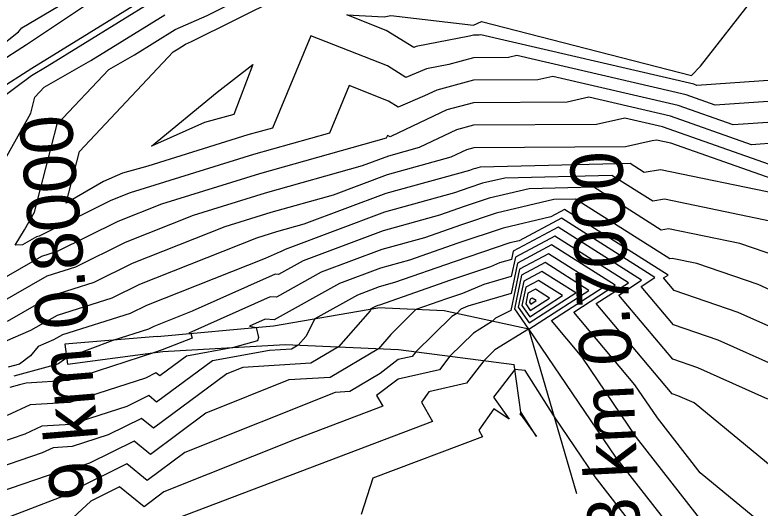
# Model space of a CAD drawing. Extents: x -549394 to -546608, y -1037055 to -1033629.
# Drawn here: x -548073.8 to -547944.9, y -1035661.2 to -1035575.9 of the extents above; entities that cross this region are included whole.
import ezdxf

# ---------------------------------------------------------------- set-up
doc = ezdxf.new("R2010")
doc.units = 0
for name, color, linetype in [('hlavni_vrst', 7, 'Continuous'), ('hrana_L', 7, 'Continuous'), ('norm_vrst', 7, 'Continuous'), ('x_popis_pricne_rezy_C1', 7, 'Continuous')]:
    doc.layers.add(name, color=color, linetype=linetype)

msp = doc.modelspace()

# ---------------------------------------------------------------- linework, layer by layer
at = {"layer": 'hlavni_vrst'}
for p, q in [((-548068.19, -1035584.8), (-548049.67, -1035573.38)), ((-548070.93, -1035586.38), (-548068.19, -1035584.8)), ((-548082.34, -1035594.86), (-548070.93, -1035586.38)), ((-547968.29, -1035593.77), (-547973.23, -1035594.84)), ((-547961.77, -1035595.29), (-547968.29, -1035593.77)), ((-547994.45, -1035595.01), (-547997.39, -1035595.8)), ((-547973.23, -1035594.84), (-547994.45, -1035595.01)), ((-547943.29, -1035601.77), (-547961.77, -1035595.29)), ((-547997.39, -1035595.8), (-548003.85, -1035598.87)), ((-548003.85, -1035598.87), (-548009.18, -1035600.33)), ((-548009.18, -1035600.33), (-548013.71, -1035602.03)), ((-548013.71, -1035602.03), (-548030.5, -1035606.72)), ((-548030.5, -1035606.72), (-548042.93, -1035610.58)), ((-547980.61, -1035607.84), (-547990.55, -1035610.18)), ((-547976.84, -1035607.75), (-547980.61, -1035607.84)), ((-547960.51, -1035618.09), (-547976.84, -1035607.75)), ((-548042.93, -1035610.58), (-548054.73, -1035615.26)), ((-547990.55, -1035610.18), (-547996.55, -1035612.2)), ((-547996.55, -1035612.2), (-548002.93, -1035614.44)), ((-548002.93, -1035614.44), (-548010.33, -1035616.48)), ((-548054.73, -1035615.26), (-548063.29, -1035619.52)), ((-547980.97, -1035615.67), (-547986.88, -1035618.83)), ((-547969.96, -1035622.66), (-547980.97, -1035615.67)), ((-548010.33, -1035616.48), (-548020.8, -1035620.4)), ((-547986.88, -1035618.83), (-547987.98, -1035624.07)), ((-547960.1, -1035618.02), (-547960.51, -1035618.09)), ((-547955.87, -1035618.9), (-547960.1, -1035618.02)), ((-547945.25, -1035622.54), (-547955.87, -1035618.9)), ((-548063.29, -1035619.52), (-548068.27, -1035621.07)), ((-548068.27, -1035621.07), (-548079.1, -1035627.29)), ((-548020.8, -1035620.4), (-548028.56, -1035624.69)), ((-547977.12, -1035627.29), (-547969.96, -1035622.66)), ((-547922.03, -1035632.93), (-547945.25, -1035622.54)), ((-547987.98, -1035624.07), (-547995.45, -1035626.25)), ((-547985.06, -1035624.02), (-547985.45, -1035625.88)), ((-547983.77, -1035623.33), (-547985.06, -1035624.02)), ((-547981.36, -1035624.86), (-547983.77, -1035623.33)), ((-548029.63, -1035624.63), (-548043.71, -1035630.91)), ((-548028.56, -1035624.69), (-548029.63, -1035624.63)), ((-547984.67, -1035627), (-547981.36, -1035624.86)), ((-547995.45, -1035626.25), (-547996.66, -1035626.76)), ((-547985.45, -1035625.88), (-547984.67, -1035627)), ((-547997.37, -1035627.53), (-547998.23, -1035628.07)), ((-547996.66, -1035626.76), (-547997.37, -1035627.53)), ((-547966.56, -1035639.84), (-547977.12, -1035627.29)), ((-547998.23, -1035628.07), (-548004.47, -1035634.15)), ((-548043.13, -1035631.77), (-548048.33, -1035633.81)), ((-548043.71, -1035630.91), (-548043.33, -1035630.98)), ((-548043.33, -1035630.98), (-548043.13, -1035631.77)), ((-548049.61, -1035634.3), (-548064.51, -1035639.13)), ((-548048.33, -1035633.81), (-548049.61, -1035634.3)), ((-548004.47, -1035634.15), (-548005.08, -1035634.94)), ((-548007.48, -1035635.49), (-548010.63, -1035637.9)), ((-548005.08, -1035634.94), (-548007.48, -1035635.49)), ((-548010.63, -1035637.9), (-548015.88, -1035641.02)), ((-548071.82, -1035639.55), (-548072.98, -1035639.86)), ((-548064.51, -1035639.13), (-548071.82, -1035639.55)), ((-548072.98, -1035639.86), (-548074.62, -1035640.33)), ((-547962.68, -1035645.56), (-547966.56, -1035639.84)), ((-548018.42, -1035641.18), (-548044.38, -1035651.57)), ((-548015.88, -1035641.02), (-548018.42, -1035641.18)), ((-547955.26, -1035655.06), (-547962.68, -1035645.56)), ((-548044.38, -1035651.57), (-548050.89, -1035656.4)), ((-548054.41, -1035653.53), (-548063.1, -1035657.85)), ((-548050.89, -1035656.4), (-548054.41, -1035653.53)), ((-547939.12, -1035668.38), (-547955.26, -1035655.06)), ((-548063.85, -1035658.55), (-548089.48, -1035668.31)), ((-548063.1, -1035657.85), (-548063.85, -1035658.55))]:
    msp.add_line(p, q, dxfattribs=at)
at = {"layer": 'hrana_L'}
for p, q in [((-548056.93, -1035571.19), (-548071.74, -1035581.11)), ((-548070.83, -1035585.15), (-548050.32, -1035572.47)), ((-548071.74, -1035581.11), (-548104.41, -1035601.7)), ((-548102.26, -1035605.09), (-548070.83, -1035585.15)), ((-548029.03, -1035629.65), (-548011.04, -1035626.55)), ((-547999.54, -1035627.06), (-548011.04, -1035626.55)), ((-547984.92, -1035630.25), (-547999.54, -1035627.06)), ((-548049.18, -1035631.53), (-548029.03, -1035629.65)), ((-547976.58, -1035658.72), (-547984.92, -1035630.25)), ((-548049.18, -1035631.53), (-548065.14, -1035632.86)), ((-548065.14, -1035632.86), (-548064.66, -1035636.28)), ((-548048.21, -1035634.12), (-548027.02, -1035632.89)), ((-548027.02, -1035632.89), (-548007.47, -1035633.76)), ((-548064.66, -1035636.28), (-548048.21, -1035634.12)), ((-548007.47, -1035633.76), (-547987.44, -1035636.37)), ((-547986.24, -1035644.99), (-547987.44, -1035636.37))]:
    msp.add_line(p, q, dxfattribs=at)
at = {"layer": 'norm_vrst'}
for p, q in [((-547955.22, -1035584.76), (-547937.68, -1035562.37)), ((-548072.6, -1035578.17), (-548058.24, -1035569.65)), ((-548040.53, -1035576.03), (-548029.87, -1035570.66)), ((-548043.21, -1035580.53), (-548027.9, -1035572.83)), ((-548060.65, -1035583.8), (-548047.86, -1035575.92)), ((-548046.05, -1035578.45), (-548040.53, -1035576.03)), ((-548016.37, -1035575.94), (-548009.91, -1035576.26)), ((-548009.55, -1035578.63), (-548016.37, -1035575.94)), ((-548009.91, -1035576.26), (-548008.76, -1035576.03)), ((-548008.76, -1035576.03), (-547994.48, -1035577.71)), ((-547994.48, -1035577.71), (-547993.1, -1035577.07)), ((-547993.1, -1035577.07), (-547956.79, -1035586.4)), ((-548092.92, -1035594.46), (-548073.15, -1035578.86)), ((-548073.15, -1035578.86), (-548072.6, -1035578.17)), ((-548053.11, -1035582.8), (-548046.05, -1035578.45)), ((-548004.8, -1035581.58), (-548009.55, -1035578.63)), ((-548022.58, -1035579.52), (-548029.24, -1035595.49)), ((-548009.36, -1035584.73), (-548022.58, -1035579.52)), ((-547995.19, -1035579.61), (-548004.39, -1035581.41)), ((-547994.48, -1035579.42), (-547995.19, -1035579.61)), ((-547993.47, -1035579.41), (-547994.48, -1035579.42)), ((-547993.23, -1035579.36), (-547993.47, -1035579.41)), ((-547956.38, -1035587.92), (-547993.23, -1035579.36)), ((-548045.56, -1035581.8), (-548044.25, -1035580.99)), ((-548044.25, -1035580.99), (-548043.21, -1035580.53)), ((-548004.39, -1035581.41), (-548004.8, -1035581.58)), ((-548062.6, -1035599.51), (-548046.4, -1035582.28)), ((-548057.55, -1035585.36), (-548053.11, -1035582.8)), ((-548046.4, -1035582.28), (-548045.56, -1035581.8)), ((-548068.71, -1035588.44), (-548060.65, -1035583.8)), ((-547994.47, -1035583.32), (-547998.76, -1035584.48)), ((-547988.41, -1035583.27), (-547994.47, -1035583.32)), ((-547987, -1035582.96), (-547988.41, -1035583.27)), ((-547957.73, -1035589.76), (-547987, -1035582.96)), ((-548066.45, -1035594.83), (-548057.55, -1035585.36)), ((-548038.82, -1035589.27), (-548032.62, -1035584.48)), ((-548032.62, -1035584.48), (-548035.94, -1035593.12)), ((-548006.16, -1035586.72), (-548009.36, -1035584.73)), ((-548002.58, -1035585.22), (-548006.16, -1035586.72)), ((-547998.76, -1035584.48), (-548002.58, -1035585.22)), ((-547956.79, -1035586.4), (-547955.22, -1035584.76)), ((-547980.76, -1035586.57), (-547983.35, -1035587.13)), ((-547959.08, -1035591.6), (-547980.76, -1035586.57)), ((-547932.68, -1035586.53), (-547955.84, -1035588.11)), ((-547994.47, -1035587.21), (-548000.81, -1035588.93)), ((-547983.35, -1035587.13), (-547994.47, -1035587.21)), ((-547955.84, -1035588.11), (-547956.38, -1035587.92)), ((-548070.31, -1035590.15), (-548068.71, -1035588.44)), ((-548050.13, -1035598.6), (-548038.82, -1035589.27)), ((-548015.97, -1035588.15), (-548019.4, -1035596.37)), ((-548009.17, -1035590.83), (-548015.97, -1035588.15)), ((-548000.81, -1035588.93), (-548002.95, -1035589.94)), ((-548071.02, -1035592.88), (-548070.31, -1035590.15)), ((-548002.95, -1035589.94), (-548007.52, -1035591.85)), ((-547974.53, -1035590.17), (-547978.29, -1035590.98)), ((-547960.42, -1035593.45), (-547974.53, -1035590.17)), ((-547952.71, -1035591.53), (-547957.73, -1035589.76)), ((-547933.2, -1035590.2), (-547952.71, -1035591.53)), ((-548007.52, -1035591.85), (-548009.17, -1035590.83)), ((-547994.46, -1035591.11), (-547999.1, -1035592.36)), ((-547978.29, -1035590.98), (-547994.46, -1035591.11)), ((-547949.57, -1035594.94), (-547959.08, -1035591.6)), ((-548081.01, -1035610.73), (-548071.02, -1035592.88)), ((-548035.94, -1035593.12), (-548040.98, -1035594.52)), ((-547999.1, -1035592.36), (-548008.63, -1035596.88)), ((-547946.43, -1035598.36), (-547960.42, -1035593.45)), ((-547933.72, -1035593.86), (-547949.57, -1035594.94)), ((-548070.38, -1035610), (-548066.45, -1035594.83)), ((-548040.98, -1035594.52), (-548050.13, -1035598.6)), ((-548029.24, -1035595.49), (-548033.48, -1035596.68)), ((-548033.48, -1035596.68), (-548050.81, -1035602.06)), ((-548019.4, -1035596.37), (-548032.49, -1035600.03)), ((-548009.37, -1035596.78), (-548009.56, -1035597.25)), ((-548008.98, -1035596.93), (-548009.37, -1035596.78)), ((-548008.89, -1035596.99), (-548008.98, -1035596.93)), ((-548008.63, -1035596.88), (-548008.89, -1035596.99)), ((-548009.56, -1035597.25), (-548031.5, -1035603.37)), ((-547963.56, -1035597.7), (-547968.17, -1035598.7)), ((-547962.83, -1035597.59), (-547963.56, -1035597.7)), ((-547960.36, -1035598.09), (-547962.83, -1035597.59)), ((-547940.15, -1035605.19), (-547960.36, -1035598.09)), ((-547934.25, -1035597.53), (-547946.43, -1035598.36)), ((-548064.91, -1035608.46), (-548062.6, -1035599.51)), ((-547995.69, -1035599.24), (-547998.41, -1035600.53)), ((-547994.44, -1035598.91), (-547995.69, -1035599.24)), ((-547968.17, -1035598.7), (-547994.44, -1035598.91)), ((-548032.49, -1035600.03), (-548053.86, -1035606.67)), ((-547998.41, -1035600.53), (-548009.41, -1035603.56)), ((-548050.81, -1035602.06), (-548055.19, -1035603.28)), ((-547967.38, -1035601.61), (-547993.3, -1035602.25)), ((-547964.97, -1035603.14), (-547967.38, -1035601.61)), ((-548055.19, -1035603.28), (-548058.46, -1035604.73)), ((-548031.5, -1035603.37), (-548048.4, -1035608.63)), ((-547995.14, -1035602.8), (-548009.64, -1035606.79)), ((-547994.61, -1035602.61), (-547995.14, -1035602.8)), ((-547994.12, -1035602.45), (-547994.61, -1035602.61)), ((-547993.3, -1035602.25), (-547994.12, -1035602.45)), ((-547962.15, -1035602.69), (-547964.97, -1035603.14)), ((-547942.03, -1035606.84), (-547962.15, -1035602.69)), ((-548058.46, -1035604.73), (-548064.91, -1035608.46)), ((-548009.41, -1035603.56), (-548018.76, -1035607.07)), ((-547989.07, -1035604.12), (-547992.93, -1035605.03)), ((-547970.53, -1035603.66), (-547989.07, -1035604.12)), ((-547963.48, -1035608.12), (-547970.53, -1035603.66)), ((-547995.26, -1035605.81), (-547997.74, -1035606.68)), ((-547992.93, -1035605.03), (-547995.26, -1035605.81)), ((-547984.84, -1035605.98), (-547991.74, -1035607.6)), ((-547973.69, -1035605.7), (-547984.84, -1035605.98)), ((-547962, -1035613.11), (-547973.69, -1035605.7)), ((-548053.86, -1035606.67), (-548057.2, -1035607.99)), ((-548018.76, -1035607.07), (-548029.51, -1035610.07)), ((-548009.64, -1035606.79), (-548023.8, -1035612.1)), ((-547997.74, -1035606.68), (-548009.87, -1035610.02)), ((-548057.2, -1035607.99), (-548069.59, -1035614.15)), ((-548048.4, -1035608.63), (-548055.96, -1035611.62)), ((-547991.74, -1035607.6), (-547995.9, -1035609)), ((-547961.47, -1035607.8), (-547963.48, -1035608.12)), ((-547940.97, -1035612.03), (-547961.47, -1035607.8)), ((-547995.9, -1035609), (-548000.34, -1035610.56)), ((-547978.72, -1035609.54), (-547981.12, -1035610.82)), ((-547960.83, -1035620.89), (-547978.72, -1035609.54)), ((-548072.12, -1035613.09), (-548070.38, -1035610)), ((-548029.51, -1035610.07), (-548037.47, -1035612.54)), ((-548009.87, -1035610.02), (-548027.05, -1035616.46)), ((-548000.34, -1035610.56), (-548010.1, -1035613.25)), ((-547981.12, -1035610.82), (-547989.36, -1035612.76)), ((-547979.28, -1035611.07), (-547986.57, -1035614.97)), ((-547963.11, -1035621.33), (-547979.28, -1035611.07)), ((-548055.96, -1035611.62), (-548066.44, -1035616.83)), ((-548023.8, -1035612.1), (-548028.52, -1035613.42)), ((-548073.73, -1035615.74), (-548072.12, -1035613.09)), ((-548037.47, -1035612.54), (-548053.49, -1035618.89)), ((-548028.52, -1035613.42), (-548032, -1035614.5)), ((-548010.1, -1035613.25), (-548023.92, -1035618.43)), ((-547989.36, -1035612.76), (-547997.19, -1035615.4)), ((-547979.84, -1035612.61), (-547987.6, -1035616.75)), ((-547965.4, -1035621.77), (-547979.84, -1035612.61)), ((-547960.78, -1035612.91), (-547962, -1035613.11)), ((-547948.42, -1035615.46), (-547960.78, -1035612.91)), ((-548070.06, -1035614.3), (-548072.48, -1035615.69)), ((-548069.59, -1035614.15), (-548070.06, -1035614.3)), ((-548032, -1035614.5), (-548052.25, -1035622.52)), ((-547986.57, -1035614.97), (-547988.17, -1035615.34)), ((-547980.4, -1035614.14), (-547987.24, -1035617.79)), ((-547967.68, -1035622.22), (-547980.4, -1035614.14)), ((-548072.48, -1035615.69), (-548073.73, -1035615.74)), ((-547997.19, -1035615.4), (-548005.53, -1035618.32)), ((-547988.17, -1035615.34), (-547997.83, -1035618.59)), ((-547941.78, -1035617.74), (-547948.42, -1035615.46)), ((-548066.44, -1035616.83), (-548069.16, -1035617.69)), ((-548027.93, -1035616.88), (-548030.51, -1035618.04)), ((-548027.82, -1035616.89), (-548027.93, -1035616.88)), ((-548027.05, -1035616.46), (-548027.82, -1035616.89)), ((-547987.6, -1035616.75), (-547987.91, -1035618.19)), ((-547981.53, -1035617.2), (-547986.51, -1035619.87)), ((-547972.24, -1035623.1), (-547981.53, -1035617.2)), ((-548069.16, -1035617.69), (-548083.11, -1035625.69)), ((-548053.49, -1035618.89), (-548060.14, -1035622.2)), ((-548030.51, -1035618.04), (-548051.01, -1035626.15)), ((-548023.92, -1035618.43), (-548028.19, -1035620.79)), ((-548005.53, -1035618.32), (-548010.56, -1035619.71)), ((-547997.83, -1035618.59), (-548008.13, -1035622.2)), ((-547989.96, -1035618.79), (-547991.56, -1035619.46)), ((-547987.91, -1035618.19), (-547989.96, -1035618.79)), ((-547987.24, -1035617.79), (-547987.94, -1035621.13)), ((-547982.09, -1035618.74), (-547986.15, -1035620.91)), ((-547974.52, -1035623.54), (-547982.09, -1035618.74)), ((-548010.56, -1035619.71), (-548017.67, -1035622.37)), ((-547991.56, -1035619.46), (-547998.48, -1035621.79)), ((-547986.51, -1035619.87), (-547988.01, -1035627.01)), ((-548028.78, -1035620.76), (-548043.13, -1035627.15)), ((-548028.19, -1035620.79), (-548028.78, -1035620.76)), ((-547987.94, -1035621.13), (-547992.71, -1035622.52)), ((-547986.15, -1035620.91), (-547987.37, -1035626.73)), ((-547982.65, -1035620.27), (-547985.79, -1035621.95)), ((-547976.8, -1035623.98), (-547982.65, -1035620.27)), ((-547965.48, -1035622.86), (-547963.11, -1035621.33)), ((-547961.6, -1035621.39), (-547960.83, -1035620.89)), ((-547959.79, -1035623.54), (-547961.6, -1035621.39)), ((-548060.14, -1035622.2), (-548067.37, -1035624.46)), ((-548052.25, -1035622.52), (-548056.99, -1035624.88)), ((-548017.67, -1035622.37), (-548028.93, -1035628.6)), ((-548008.13, -1035622.2), (-548010.78, -1035622.93)), ((-547998.48, -1035621.79), (-548010.73, -1035626.08)), ((-547992.71, -1035622.52), (-547996.4, -1035624.07)), ((-547985.79, -1035621.95), (-547986.73, -1035626.44)), ((-547983.21, -1035621.8), (-547985.42, -1035622.99)), ((-547979.08, -1035624.42), (-547983.21, -1035621.8)), ((-547973.24, -1035625.81), (-547967.68, -1035622.22)), ((-547969.36, -1035624.34), (-547965.4, -1035621.77)), ((-548010.78, -1035622.93), (-548014.54, -1035624.34)), ((-547996.4, -1035624.07), (-547999.12, -1035624.98)), ((-547985.42, -1035622.99), (-547986.09, -1035626.16)), ((-547984.88, -1035630.24), (-547974.52, -1035623.54)), ((-547984.84, -1035629.17), (-547976.8, -1035623.98)), ((-547981, -1035628.76), (-547972.24, -1035623.1)), ((-547959.91, -1035629.49), (-547965.48, -1035622.86)), ((-547948.72, -1035627.34), (-547959.79, -1035623.54)), ((-548067.37, -1035624.46), (-548075.09, -1035628.89)), ((-548056.99, -1035624.88), (-548066.47, -1035627.85)), ((-548014.54, -1035624.34), (-548021.93, -1035628.43)), ((-547999.12, -1035624.98), (-548004.43, -1035626.84)), ((-547984.7, -1035625.06), (-547984.81, -1035625.59)), ((-547984.75, -1035628.09), (-547979.08, -1035624.42)), ((-547984.33, -1035624.87), (-547984.7, -1035625.06)), ((-547984.58, -1035625.91), (-547983.64, -1035625.3)), ((-547983.64, -1035625.3), (-547984.33, -1035624.87)), ((-547960.02, -1035635.44), (-547969.36, -1035624.34)), ((-548051.01, -1035626.15), (-548053.84, -1035627.56)), ((-548011.42, -1035626.31), (-548012.21, -1035626.75)), ((-548011.01, -1035626.16), (-548011.42, -1035626.31)), ((-548010.73, -1035626.08), (-548011.01, -1035626.16)), ((-547986.73, -1035626.44), (-547984.84, -1035629.17)), ((-547986.09, -1035626.16), (-547984.75, -1035628.09)), ((-547984.81, -1035625.59), (-547984.58, -1035625.91)), ((-547960.14, -1035641.39), (-547973.24, -1035625.81)), ((-548066.47, -1035627.85), (-548071.08, -1035630.49)), ((-548053.84, -1035627.56), (-548065.57, -1035631.23)), ((-548043.13, -1035627.15), (-548049.77, -1035629.79)), ((-548012.37, -1035627.08), (-548017.84, -1035633.3)), ((-548012.21, -1035626.75), (-548012.37, -1035627.08)), ((-548004.43, -1035626.84), (-548008.75, -1035631.18)), ((-547988.01, -1035627.01), (-547990.68, -1035628.34)), ((-547988.01, -1035627.01), (-547988.01, -1035627.01)), ((-547988.01, -1035627.01), (-547988.01, -1035627.01)), ((-547987.37, -1035626.73), (-547984.95, -1035630.22)), ((-547918.06, -1035641.06), (-547948.72, -1035627.34)), ((-548030.48, -1035628.51), (-548033.2, -1035629.73)), ((-548028.93, -1035628.6), (-548030.48, -1035628.51)), ((-548021.93, -1035628.43), (-548023.47, -1035631.48)), ((-547991.18, -1035628.88), (-547994.5, -1035630.94)), ((-547990.68, -1035628.34), (-547991.18, -1035628.88)), ((-547975.7, -1035635.07), (-547981, -1035628.76)), ((-548071.08, -1035630.49), (-548078.1, -1035633.5)), ((-548050.69, -1035630.24), (-548056.84, -1035632.17)), ((-548049.77, -1035629.79), (-548050.69, -1035630.24)), ((-548033.2, -1035629.73), (-548032.07, -1035629.93)), ((-548032.07, -1035629.93), (-548031.63, -1035631.67)), ((-547984.98, -1035630.24), (-547990.76, -1035633.81)), ((-547984.95, -1035630.22), (-547984.98, -1035630.23)), ((-547984.98, -1035630.23), (-547984.98, -1035630.24)), ((-547984.83, -1035630.3), (-547984.88, -1035630.24)), ((-547969.87, -1035652.36), (-547984.83, -1035630.3)), ((-547952.19, -1035632.14), (-547959.91, -1035629.49)), ((-548065.57, -1035631.23), (-548067.07, -1035632.09)), ((-548031.63, -1035631.67), (-548031.82, -1035632.26)), ((-548023.47, -1035631.48), (-548024.79, -1035632.99)), ((-548008.75, -1035631.18), (-548010.88, -1035633.61)), ((-547994.5, -1035630.94), (-547998.57, -1035634.92)), ((-548067.07, -1035632.09), (-548069.73, -1035633.23)), ((-548056.84, -1035632.17), (-548064.82, -1035635.17)), ((-548031.82, -1035632.26), (-548035.97, -1035633.41)), ((-548024.79, -1035632.99), (-548025.95, -1035633.67)), ((-547930.82, -1035641.7), (-547952.19, -1035632.14)), ((-548069.73, -1035633.23), (-548071.07, -1035634.87)), ((-548035.97, -1035633.41), (-548044.08, -1035634.88)), ((-548029.75, -1035633.91), (-548039.63, -1035635.7)), ((-548025.95, -1035633.67), (-548029.75, -1035633.91)), ((-548017.84, -1035633.3), (-548022.59, -1035636.12)), ((-548010.88, -1035633.61), (-548019.24, -1035638.57)), ((-547990.76, -1035633.81), (-547992.68, -1035635.69)), ((-548071.07, -1035634.87), (-548073, -1035636.3)), ((-548064.82, -1035635.17), (-548066.33, -1035636.28)), ((-548039.63, -1035635.7), (-548049.26, -1035642.84)), ((-548044.08, -1035634.88), (-548048.71, -1035638.32)), ((-547998.57, -1035634.92), (-548000.38, -1035637.25)), ((-547992.68, -1035635.69), (-547995.68, -1035639.56)), ((-547966.27, -1035648.96), (-547975.7, -1035635.07)), ((-547955.66, -1035636.94), (-547960.02, -1035635.44)), ((-548073, -1035636.3), (-548074.94, -1035636.82)), ((-548066.33, -1035636.28), (-548073.96, -1035638.34)), ((-548034.34, -1035636.84), (-548037.12, -1035637.95)), ((-548022.59, -1035636.12), (-548034.34, -1035636.84)), ((-547943.58, -1035642.34), (-547955.66, -1035636.94)), ((-548049.38, -1035637.78), (-548051.2, -1035638.69)), ((-548037.12, -1035637.95), (-548049.8, -1035647.36)), ((-548048.71, -1035638.32), (-548049.38, -1035637.78)), ((-548000.38, -1035637.25), (-548007.51, -1035638.88)), ((-547987.33, -1035637.19), (-547991.02, -1035641.99)), ((-547985.56, -1035637.4), (-547987.33, -1035637.19)), ((-547980.48, -1035645.4), (-547985.56, -1035637.4)), ((-548051.2, -1035638.69), (-548064.3, -1035642.94)), ((-548026.38, -1035639.01), (-548040.75, -1035644.76)), ((-548019.24, -1035638.57), (-548026.38, -1035639.01)), ((-548007.51, -1035638.88), (-548011.22, -1035641.73)), ((-547995.68, -1035639.56), (-548002.18, -1035641.05)), ((-548050.64, -1035641.72), (-548054.42, -1035643.6)), ((-548049.26, -1035642.84), (-548050.64, -1035641.72)), ((-548011.22, -1035641.73), (-548010.16, -1035643.56)), ((-548002.18, -1035641.05), (-548003.47, -1035642.86)), ((-547991.02, -1035641.99), (-547988.3, -1035645.79)), ((-547959.13, -1035641.74), (-547960.14, -1035641.39)), ((-547956.34, -1035642.99), (-547959.13, -1035641.74)), ((-548071.11, -1035643.32), (-548075.09, -1035645.15)), ((-548064.3, -1035642.94), (-548071.11, -1035643.32)), ((-548003.47, -1035642.86), (-548001.54, -1035646.2)), ((-547933.73, -1035661.65), (-547956.34, -1035642.99)), ((-548054.42, -1035643.6), (-548064.1, -1035646.74)), ((-548010.16, -1035643.56), (-548025, -1035649.17)), ((-547990.96, -1035643.99), (-547993.58, -1035647.7)), ((-547988.3, -1035645.79), (-547990.96, -1035643.99)), ((-547986.29, -1035644.62), (-547986.47, -1035644.85)), ((-547986.21, -1035644.63), (-547986.29, -1035644.62)), ((-547983.56, -1035648.8), (-547986.21, -1035644.63)), ((-548051.9, -1035645.65), (-548057.63, -1035648.51)), ((-548049.8, -1035647.36), (-548051.9, -1035645.65)), ((-548040.75, -1035644.76), (-548050.34, -1035651.88)), ((-547988.3, -1035645.79), (-547988.3, -1035645.79)), ((-547988.3, -1035645.79), (-547988.3, -1035645.79)), ((-547986.47, -1035644.85), (-547986.34, -1035645.03)), ((-547986.34, -1035645.03), (-547986.21, -1035645.13)), ((-547986.21, -1035645.13), (-547983.56, -1035648.8)), ((-547973.46, -1035655.76), (-547980.48, -1035645.4)), ((-548069.13, -1035647.03), (-548072.07, -1035648.37)), ((-548064.1, -1035646.74), (-548069.13, -1035647.03)), ((-548001.54, -1035646.2), (-548049.35, -1035664.28)), ((-548072.07, -1035648.37), (-548087.89, -1035653.8)), ((-548057.63, -1035648.51), (-548063.89, -1035650.54)), ((-547993.58, -1035647.7), (-547992.92, -1035648.84)), ((-548053.16, -1035649.59), (-548060.85, -1035653.42)), ((-548050.34, -1035651.88), (-548053.16, -1035649.59)), ((-548025, -1035649.17), (-548048, -1035658.38)), ((-547992.92, -1035648.84), (-548011.89, -1035656.01)), ((-547948.24, -1035672.03), (-547966.27, -1035648.96)), ((-548067.15, -1035650.73), (-548069.05, -1035651.6)), ((-548063.89, -1035650.54), (-548067.15, -1035650.73)), ((-548069.05, -1035651.6), (-548091.84, -1035659.41)), ((-547954.42, -1035672.11), (-547969.87, -1035652.36)), ((-548060.85, -1035653.42), (-548063.69, -1035654.34)), ((-548066.03, -1035654.82), (-548088.34, -1035662.47)), ((-548065.16, -1035654.43), (-548066.03, -1035654.82)), ((-548063.69, -1035654.34), (-548065.16, -1035654.43)), ((-548011.89, -1035656.01), (-548013.88, -1035662.29)), ((-547966.27, -1035664.95), (-547973.46, -1035655.76)), ((-548055.67, -1035657.46), (-548060.65, -1035659.94)), ((-548051.43, -1035660.92), (-548055.67, -1035657.46)), ((-548048, -1035658.38), (-548051.43, -1035660.92)), ((-548060.65, -1035659.94), (-548065.81, -1035664.7))]:
    msp.add_line(p, q, dxfattribs=at)

# ---------------------------------------------------------------- texts
at = {"layer": 'x_popis_pricne_rezy_C1'}
for s, rotation, p in [('PŘ 9 km 0.8000', 94.748, (-548056.85, -1035679.5)), ('PŘ 8 km 0.7000', 92.7724, (-547964.61, -1035686.09))]:
    msp.add_text(s, height=9.0627, rotation=rotation, dxfattribs=at).set_placement(p)

doc.saveas('drawing.dxf')
